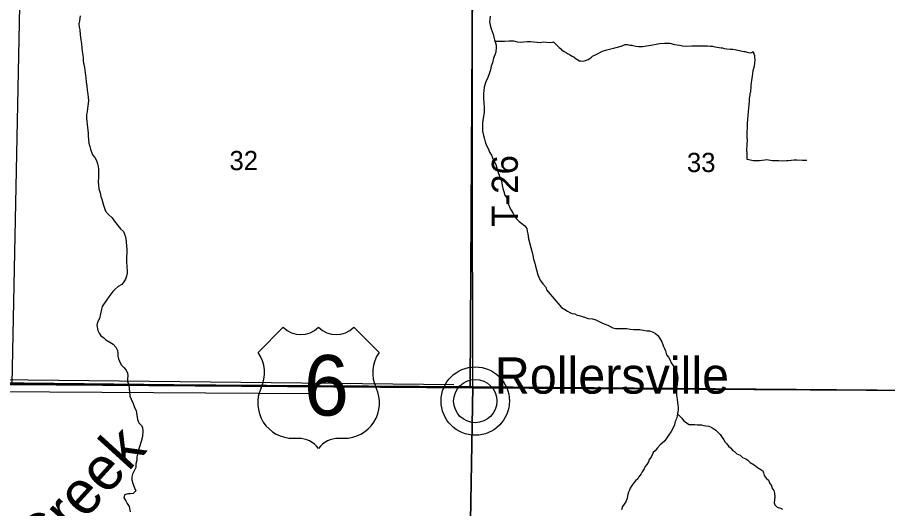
# Model space of a CAD drawing. Extents: x 1588073 to 2013523, y 1090242 to 1357120.
# Drawn here: x 1721913 to 1731928, y 1216995 to 1222644 of the extents above; entities that cross this region are included whole.
import ezdxf

# ---------------------------------------------------------------- set-up
doc = ezdxf.new("R2010")
doc.units = 0
for name, color, linetype in [('GM_X_Minor_River', 7, 'Continuous'), ('GM_X_Minor_River_Text', 7, 'Continuous'), ('GM_X_Section', 7, 'Continuous'), ('GM_X_Section_Text', 7, 'Continuous'), ('GM_X_Township', 7, 'Continuous'), ('GM_X_Township_Road', 7, 'Continuous'), ('GM_X_Township_Road_Text', 7, 'Continuous'), ('GM_X_Unincorporated', 7, 'Continuous'), ('GM_X_Unincorporated_Location', 7, 'Continuous'), ('GM_X_Unincorporated_Text', 7, 'Continuous'), ('GM_X_US_Location', 7, 'Continuous'), ('GM_X_US_Route', 7, 'Continuous'), ('GM_X_US_Shield', 7, 'Continuous')]:
    doc.layers.add(name, color=color, linetype=linetype)

msp = doc.modelspace()

# ---------------------------------------------------------------- linework, layer by layer
at = {"layer": 'GM_X_Minor_River'}
for p, q in [((1720969, 1218488), (1726937, 1218421)), ((1720674, 1218347), (1725283, 1218318))]:
    msp.add_line(p, q, dxfattribs=at)
for points in [[(1722636, 1222663), (1722628, 1222606), (1722622, 1222568), (1722626, 1222532), (1722630, 1222502), (1722634, 1222442), (1722644, 1222386), (1722652, 1222340), (1722656, 1222293), (1722660, 1222257), (1722666, 1222209), (1722670, 1222179), (1722672, 1222141), (1722676, 1222103), (1722684, 1222067), (1722690, 1222036), (1722694, 1222008), (1722696, 1221980), (1722700, 1221948), (1722706, 1221902), (1722712, 1221852), (1722718, 1221806), (1722724, 1221761), (1722728, 1221721), (1722730, 1221687), (1722728, 1221655)], [(1727353, 1222658), (1727349, 1222624), (1727347, 1222593), (1727353, 1222553), (1727365, 1222513), (1727379, 1222483), (1727387, 1222451), (1727397, 1222417), (1727405, 1222385), (1727417, 1222353), (1727423, 1222325), (1727423, 1222296), (1727419, 1222244), (1727407, 1222212), (1727393, 1222176), (1727383, 1222122), (1727367, 1222084), (1727359, 1222040), (1727347, 1222007), (1727325, 1221941), (1727310, 1221913), (1727298, 1221879), (1727286, 1221841), (1727282, 1221803), (1727276, 1221765), (1727276, 1221706), (1727280, 1221664), (1727284, 1221604), (1727286, 1221552), (1727274, 1221484), (1727266, 1221429), (1727266, 1221401), (1727268, 1221371), (1727268, 1221335), (1727276, 1221287), (1727284, 1221257), (1727298, 1221211), (1727314, 1221169), (1727336, 1221128), (1727348, 1221094), (1727370, 1221060), (1727394, 1221000), (1727418, 1220952), (1727436, 1220898), (1727448, 1220859), (1727461, 1220819), (1727475, 1220791), (1727485, 1220761), (1727493, 1220709), (1727499, 1220675), (1727513, 1220641), (1727525, 1220600), (1727543, 1220572), (1727555, 1220530), (1727563, 1220498), (1727587, 1220440), (1727617, 1220398), (1727631, 1220366), (1727657, 1220328), (1727687, 1220297), (1727719, 1220273), (1727753, 1220245), (1727775, 1220215), (1727781, 1220187), (1727789, 1220155), (1727797, 1220099), (1727807, 1220055), (1727821, 1219996), (1727835, 1219954), (1727847, 1219906), (1727855, 1219862), (1727867, 1219818), (1727877, 1219784), (1727887, 1219741), (1727903, 1219685), (1727916, 1219657), (1727928, 1219623), (1727962, 1219579), (1727994, 1219543), (1728004, 1219511)], [(1727409, 1222374), (1727429, 1222369), (1727475, 1222371), (1727521, 1222369), (1727573, 1222375), (1727624, 1222373), (1727664, 1222361), (1727704, 1222359), (1727742, 1222361), (1727782, 1222365), (1727818, 1222367), (1727856, 1222361), (1727896, 1222359), (1727931, 1222357), (1727963, 1222361), (1728003, 1222359), (1728039, 1222357), (1728075, 1222359), (1728083, 1222361)], [(1728083, 1222361), (1728130, 1222317), (1728148, 1222298), (1728162, 1222286), (1728175, 1222270), (1728205, 1222253), (1728231, 1222238), (1728246, 1222228), (1728278, 1222211), (1728300, 1222198), (1728320, 1222188), (1728349, 1222165), (1728365, 1222155), (1728381, 1222146), (1728399, 1222144), (1728425, 1222141), (1728453, 1222148), (1728483, 1222158), (1728501, 1222173), (1728520, 1222187), (1728534, 1222198), (1728589, 1222223), (1728633, 1222246), (1728648, 1222256), (1728696, 1222272), (1728712, 1222276), (1728789, 1222294), (1728861, 1222314), (1728910, 1222331), (1728934, 1222333), (1728960, 1222326), (1728984, 1222325), (1728998, 1222319), (1729030, 1222314), (1729062, 1222311), (1729108, 1222310), (1729154, 1222315), (1729182, 1222320), (1729226, 1222329), (1729305, 1222345), (1729361, 1222348), (1729393, 1222349), (1729421, 1222346), (1729439, 1222342), (1729459, 1222335), (1729477, 1222333), (1729533, 1222323), (1729553, 1222319), (1729568, 1222316), (1729600, 1222314), (1729675, 1222316), (1729737, 1222318), (1729781, 1222317), (1729817, 1222318), (1729841, 1222318), (1729857, 1222315), (1729885, 1222312), (1729913, 1222312), (1729939, 1222307), (1729967, 1222302), (1729991, 1222298), (1730013, 1222295), (1730027, 1222293), (1730046, 1222288), (1730080, 1222283), (1730116, 1222280), (1730148, 1222280), (1730184, 1222271), (1730224, 1222264), (1730272, 1222252), (1730288, 1222250), (1730310, 1222245), (1730326, 1222241), (1730346, 1222236), (1730366, 1222242), (1730382, 1222250), (1730389, 1222223), (1730395, 1222205), (1730398, 1222177), (1730402, 1222159), (1730401, 1222143), (1730397, 1222129), (1730395, 1222111), (1730388, 1222067), (1730379, 1222031), (1730372, 1221997), (1730369, 1221969), (1730366, 1221943), (1730362, 1221923), (1730359, 1221893), (1730356, 1221861), (1730354, 1221837), (1730351, 1221801), (1730349, 1221783), (1730344, 1221769), (1730342, 1221751), (1730339, 1221731), (1730337, 1221709), (1730334, 1221679), (1730331, 1221637), (1730323, 1221563)], [(1722728, 1221655), (1722724, 1221625), (1722720, 1221595), (1722716, 1221559), (1722710, 1221527), (1722710, 1221485), (1722712, 1221452), (1722718, 1221414), (1722720, 1221376), (1722722, 1221348), (1722726, 1221312), (1722728, 1221282), (1722730, 1221238), (1722736, 1221198), (1722746, 1221161), (1722756, 1221129), (1722776, 1221063), (1722804, 1221031), (1722824, 1220997), (1722836, 1220959), (1722844, 1220929), (1722846, 1220900), (1722846, 1220804), (1722844, 1220756), (1722850, 1220674), (1722866, 1220627), (1722872, 1220585), (1722884, 1220553), (1722900, 1220497), (1722916, 1220451), (1722928, 1220417), (1722960, 1220377), (1723002, 1220340), (1723028, 1220306), (1723068, 1220250), (1723100, 1220212), (1723133, 1220180), (1723159, 1220122), (1723165, 1220065), (1723169, 1220011), (1723171, 1219983), (1723171, 1219945), (1723169, 1219887), (1723169, 1219835), (1723171, 1219776), (1723175, 1219730), (1723177, 1219702), (1723168, 1219668), (1723156, 1219634), (1723140, 1219602), (1723114, 1219574), (1723072, 1219548), (1723040, 1219518), (1723012, 1219492), (1722966, 1219429), (1722940, 1219391), (1722889, 1219321), (1722883, 1219287), (1722871, 1219235), (1722857, 1219182), (1722835, 1219138), (1722829, 1219106), (1722839, 1219042), (1722853, 1219014), (1722875, 1218982), (1722903, 1218962), (1722931, 1218936), (1722976, 1218909), (1723016, 1218885), (1723048, 1218853), (1723064, 1218813), (1723068, 1218783), (1723068, 1218749), (1723076, 1218717), (1723090, 1218689), (1723108, 1218649), (1723138, 1218618), (1723166, 1218586), (1723182, 1218554), (1723184, 1218526), (1723182, 1218484), (1723180, 1218456), (1723194, 1218424), (1723198, 1218374), (1723202, 1218337), (1723208, 1218287), (1723222, 1218255), (1723244, 1218205), (1723262, 1218159), (1723282, 1218123), (1723288, 1218071), (1723296, 1218020), (1723310, 1217980), (1723340, 1217952), (1723352, 1217922), (1723358, 1217888), (1723354, 1217826), (1723336, 1217767), (1723314, 1217695), (1723298, 1217635), (1723288, 1217589)], [(1730323, 1221563), (1730320, 1221515), (1730315, 1221469), (1730312, 1221427), (1730311, 1221393), (1730312, 1221363), (1730310, 1221341), (1730310, 1221287), (1730310, 1221261), (1730311, 1221229), (1730308, 1221185), (1730306, 1221111), (1730308, 1221096), (1730307, 1221080), (1730309, 1221056), (1730308, 1221012), (1730332, 1221010), (1730380, 1221000), (1730408, 1221000), (1730456, 1221000), (1730486, 1221002), (1730514, 1221005), (1730536, 1221008), (1730602, 1220999), (1730676, 1220997), (1730714, 1220994), (1730764, 1220997), (1730784, 1220998), (1730818, 1221003), (1730848, 1221004), (1730862, 1221006), (1730882, 1221006), (1730950, 1221002), (1731000, 1221001)], [(1728004, 1219511), (1728177, 1219307), (1728215, 1219283), (1728243, 1219265), (1728273, 1219251), (1728299, 1219239), (1728329, 1219233), (1728355, 1219219), (1728379, 1219215), (1728429, 1219199), (1728481, 1219183), (1728531, 1219177), (1728572, 1219165), (1728602, 1219149), (1728640, 1219131), (1728684, 1219111), (1728710, 1219104), (1728744, 1219086), (1728768, 1219072), (1728796, 1219066), (1728820, 1219066), (1728862, 1219068), (1728894, 1219066), (1728928, 1219066), (1728968, 1219058), (1729003, 1219054), (1729047, 1219056), (1729077, 1219056), (1729117, 1219047), (1729157, 1219041), (1729189, 1219041), (1729229, 1219025), (1729259, 1219007), (1729285, 1218987), (1729309, 1218951), (1729331, 1218913), (1729343, 1218881), (1729350, 1218859), (1729362, 1218837), (1729372, 1218809), (1729384, 1218763), (1729408, 1218737), (1729426, 1218702), (1729436, 1218670), (1729456, 1218646), (1729470, 1218624), (1729482, 1218602), (1729497, 1218568), (1729507, 1218546), (1729511, 1218520), (1729513, 1218496), (1729511, 1218470), (1729505, 1218430), (1729503, 1218400), (1729499, 1218372), (1729497, 1218330), (1729499, 1218302), (1729503, 1218274), (1729505, 1218250), (1729512, 1218217), (1729516, 1218189), (1729518, 1218159), (1729518, 1218127), (1729512, 1218095), (1729506, 1218059), (1729498, 1218027), (1729484, 1217995), (1729474, 1217957), (1729460, 1217925), (1729438, 1217882), (1729410, 1217844), (1729387, 1217808), (1729365, 1217774), (1729333, 1217748), (1729311, 1217728), (1729281, 1217693), (1729253, 1217661), (1729231, 1217641), (1729209, 1217587), (1729185, 1217559), (1729175, 1217531), (1729159, 1217503), (1729139, 1217478), (1729127, 1217454), (1729103, 1217418), (1729091, 1217394), (1729067, 1217360), (1729053, 1217336), (1729027, 1217316), (1729009, 1217292), (1728985, 1217261), (1728965, 1217231), (1728958, 1217207), (1728948, 1217185), (1728940, 1217159), (1728930, 1217115), (1728914, 1217071), (1728898, 1217045), (1728878, 1217018), (1728866, 1216982)], [(1728004, 1219511), (1728004, 1219510)], [(1729514, 1218106), (1729512, 1218085), (1729536, 1218059), (1729560, 1218035), (1729580, 1218009), (1729614, 1217983), (1729644, 1217963), (1729711, 1217961), (1729735, 1217959), (1729757, 1217959), (1729785, 1217958), (1729813, 1217950), (1729837, 1217946), (1729871, 1217942), (1729907, 1217928), (1729951, 1217896), (1730001, 1217848), (1730025, 1217812), (1730042, 1217784), (1730058, 1217758), (1730080, 1217738), (1730096, 1217712), (1730120, 1217694), (1730142, 1217666), (1730166, 1217650), (1730194, 1217624), (1730230, 1217610), (1730260, 1217584), (1730297, 1217566), (1730319, 1217552), (1730345, 1217524), (1730391, 1217500), (1730433, 1217466), (1730471, 1217444), (1730493, 1217428), (1730499, 1217406), (1730509, 1217374), (1730529, 1217346), (1730558, 1217322), (1730574, 1217284), (1730592, 1217262), (1730598, 1217234), (1730618, 1217202), (1730628, 1217172), (1730632, 1217130), (1730626, 1217096), (1730624, 1217060), (1730632, 1217038), (1730657, 1217012), (1730697, 1217000), (1730719, 1216988)], [(1723288, 1217589), (1723286, 1217553), (1723276, 1217511), (1723276, 1217468), (1723238, 1217390), (1723230, 1217362), (1723232, 1217326), (1723242, 1217282), (1723260, 1217232), (1723276, 1217199), (1723244, 1217167), (1723214, 1217165), (1723184, 1217165), (1723147, 1217153), (1723137, 1217119), (1723161, 1217083), (1723177, 1217055), (1723198, 1217019), (1723210, 1216957)]]:
    msp.add_lwpolyline(points, dxfattribs=at)
at = {"layer": 'GM_X_Section'}
for points in [[(1721959, 1223720), (1727155, 1223716), (1727126, 1218396), (1721852, 1218428)], [(1727155, 1223716), (1732467, 1223652), (1732414, 1218356), (1732272, 1218355), (1727156, 1218396), (1727126, 1218396)], [(1721724, 1218428), (1721852, 1218428), (1727126, 1218396), (1727156, 1218396), (1727068, 1213330), (1721572, 1213251)], [(1727156, 1218396), (1732272, 1218355), (1732351, 1213370), (1727068, 1213330)]]:
    msp.add_lwpolyline(points, close=True, dxfattribs=at)
at = {"layer": 'GM_X_Township'}
for points in [[(1732329, 1218355), (1727153, 1218382), (1716495, 1218461), (1716635, 1223742), (1716775, 1229053), (1716842, 1231693), (1716902, 1234359), (1716964, 1236948), (1717023, 1239608), (1717083, 1242245), (1722393, 1242206), (1727658, 1242156), (1732981, 1242108)], [(1716424, 1215762), (1716495, 1218461), (1727153, 1218382), (1732329, 1218355), (1737614, 1218254), (1737690, 1218251), (1740316, 1218175), (1742970, 1218171), (1745603, 1218172), (1747148, 1218171), (1748292, 1218179), (1748310, 1212997)]]:
    msp.add_lwpolyline(points, dxfattribs=at)
at = {"layer": 'GM_X_Township_Road'}
for points in [[(1727153, 1218382), (1727153, 1218382), (1727149, 1223695), (1727273, 1228997)], [(1727118, 1215925), (1727153, 1218382)]]:
    msp.add_lwpolyline(points, dxfattribs=at)
at = {"layer": 'GM_X_Unincorporated'}
for radius in [393, 249]:
    msp.add_circle((1727183, 1218232), radius, dxfattribs=at)
at = {"layer": 'GM_X_Unincorporated_Location'}
msp.add_line((1727183, 1218232), (1727183, 1218232), dxfattribs=at)
at = {"layer": 'GM_X_US_Route'}
msp.add_lwpolyline([(1716482, 1218504), (1727153, 1218382), (1732329, 1218355), (1737614, 1218254), (1737690, 1218251), (1740316, 1218175), (1742970, 1218171)], dxfattribs=at)
at = {"layer": 'GM_X_US_Shield'}
for p, q in [((1724973, 1219080), (1724683, 1218790)), ((1726075, 1218790), (1725785, 1219080)), ((1725089, 1217804), (1725147, 1217804)), ((1725611, 1217804), (1725669, 1217804))]:
    msp.add_line(p, q, dxfattribs=at)
for centre, radius, start, end in [((1725176, 1219287), 290, 225.573, 314.427), ((1725582, 1219287), 290, 225.573, 314.427), ((1724351, 1218557), 406, 334.5471, 35.0009), ((1726408, 1218557), 406, 144.9991, 205.4529), ((1725085, 1218210), 406, 154.8319, 270.6383), ((1725674, 1218210), 406, 269.3617, 25.1681), ((1725147, 1217513), 290, 36.8699, 90), ((1725611, 1217513), 290, 90, 143.1301)]:
    msp.add_arc(centre, radius, start, end, dxfattribs=at)

# ---------------------------------------------------------------- texts
at = {"layer": 'GM_X_Minor_River_Text'}
msp.add_text('Creek', height=500.3, rotation=47.7445, dxfattribs=at).set_placement((1722214, 1216340))
at = {"layer": 'GM_X_Section_Text'}
for s, p in [('32', (1724354, 1220887)), ('33', (1729619, 1220865))]:
    msp.add_text(s, height=221, rotation=0, dxfattribs=at).set_placement(p)
at = {"layer": 'GM_X_Township_Road_Text'}
msp.add_text('T-26', height=300, rotation=90, dxfattribs=at).set_placement((1727673, 1220236))
at = {"layer": 'GM_X_Unincorporated_Text'}
msp.add_text('Rollersville', height=417, rotation=0, dxfattribs=at).set_placement((1727408, 1218317))
at = {"layer": 'GM_X_US_Location'}
for s in ['0', '/']:
    msp.add_text(s, height=1, dxfattribs=at).set_placement((1725379, 1218407))
msp.add_text('6', height=1, rotation=0, dxfattribs=at).set_placement((1725278, 1218200))
at = {"layer": 'GM_X_US_Shield'}
msp.add_text('6', height=696, dxfattribs=at).set_placement((1725211, 1218065))

doc.saveas('drawing.dxf')
